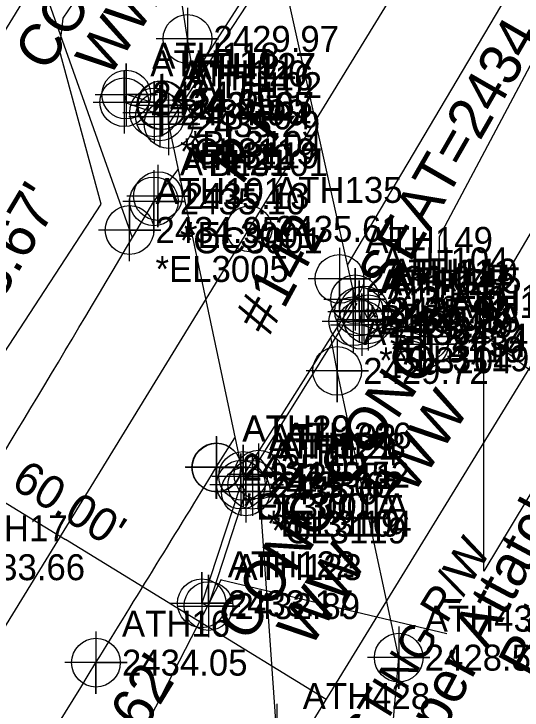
# Model space of a CAD drawing. Extents: x 983976 to 986421, y 758828 to 761458.
# Drawn here: x 984809.7 to 984858.6, y 760052.1 to 760119.1 of the extents above; entities that cross this region are included whole.
import ezdxf

# ---------------------------------------------------------------- set-up
doc = ezdxf.new("R2010")
doc.units = 0
for name, color, linetype in [('COGO Default Chain', 7, 'Continuous'), ('CTL Secondary Horizontal and Vertical Leader', 7, 'Continuous'), ('CTL Secondary Horizontal and Vertical Text', 7, 'Continuous'), ('CTL Sheet Text', 7, 'Continuous'), ('Exist DTM Drainline Cogo Point CELL', 7, 'Continuous'), ('Exist DTM Regular Point CELL', 7, 'Continuous'), ('Exist DTM Regular Point Underwater CELL', 7, 'Continuous'), ('Exist Guardrail', 7, 'Continuous'), ('Exist Horizontal Alignment', 7, 'Continuous'), ('Exist Hydro Jurisdictional Stream or Body of Water', 7, 'Continuous'), ('Exist Property Iron Pin CELL', 7, 'Continuous'), ('Exist Property Iron Pin Cogo Elevation', 7, 'Continuous'), ('Exist Property Iron Pin Cogo Number', 7, 'Continuous'), ('Exist Property Iron Pin Text', 7, 'Continuous'), ('Exist Right of Way Line', 7, 'Continuous'), ('Exist Right of Way Line Text', 7, 'Continuous'), ('Exist Right of Way Width CELL', 7, 'Continuous'), ('Exist Roads EOP', 7, 'Continuous'), ('Exist Roads EOP Cogo Point CELL', 7, 'Continuous'), ('Exist Roads Soil', 7, 'Continuous'), ('Exist Roads Soil Cogo Comment', 7, 'Continuous'), ('Exist Roads Soil Cogo Elevation', 7, 'Continuous'), ('Exist Roads Soil Cogo Number', 7, 'Continuous'), ('Exist Roads Soil Cogo Point CELL', 7, 'Continuous'), ('Exist Structure Major Bridge Seat Cogo Comment', 7, 'Continuous'), ('Exist Structure Major Bridge Seat Cogo Elevation', 7, 'Continuous'), ('Exist Structure Major Bridge Seat Cogo Number', 7, 'Continuous'), ('Exist Structure Major Bridge Seat Cogo Point CELL', 7, 'Continuous'), ('Exist Structure Major Bridge Seat Top Elevation', 7, 'Continuous'), ('Exist Structure Major Bridge WW', 7, 'Continuous'), ('Exist Structure Major Bridge WW Cogo Comment', 7, 'Continuous'), ('Exist Structure Major Bridge WW Cogo Elevation', 7, 'Continuous'), ('Exist Structure Major Bridge WW Cogo Number', 7, 'Continuous'), ('Exist Structure Major Bridge WW Cogo Point CELL', 7, 'Continuous'), ('Exist Structure Major Bridge WW Text', 7, 'Continuous'), ('Exist Structure Major Deck Tunnel Box Culvert', 7, 'Continuous'), ('Exist Structure Major Deck Tunnel Box Culvert Cogo Comment', 7, 'Continuous'), ('Exist Structure Major Deck Tunnel Box Culvert Cogo Elevation', 7, 'Continuous'), ('Exist Structure Major Deck Tunnel Box Culvert Cogo Number', 7, 'Continuous'), ('Exist Structure Major Deck Tunnel Box Culvert Cogo Point CELL', 7, 'Continuous'), ('Exist Structure Major Deck Tunnel Box Culvert Text', 7, 'Continuous'), ('Exist Utilities Power Transformer CELL', 7, 'Continuous'), ('Exist Utilities Telephone Pole Leader', 7, 'Continuous'), ('Exist Utilities Telephone Pole Text', 7, 'Continuous'), ('Exist Utilities Telephone UG Cable SUE LOS C', 7, 'Continuous'), ('Exist Vegetation Woods Line', 7, 'Continuous')]:
    doc.layers.add(name, color=color, linetype=linetype)

msp = doc.modelspace()

# ---------------------------------------------------------------- linework, layer by layer
at = {"layer": 'COGO Default Chain'}
msp.add_line((984790.47, 760030.234), (984862.074, 760146.899), dxfattribs=at)
at = {"layer": 'Exist Guardrail'}
for p, q in [((984824.469, 760109.232), (984834.503, 760124.823)), ((984842.671, 760091.224), (984832.126, 760074.336))]:
    msp.add_line(p, q, dxfattribs=at)
at = {"layer": 'Exist Horizontal Alignment'}
msp.add_line((984790.47, 760030.234), (984862.074, 760146.899), dxfattribs=at)
at = {"layer": 'Exist Hydro Jurisdictional Stream or Body of Water'}
for points in [[(984827.066, 760112.31), (984826.358, 760116.652), (984820.043, 760157.784), (984809.834, 760195.884), (984798.987, 760237.514), (984800.737, 760260.977), (984804.203, 760288.203), (984847.36, 760365.08), (984869.621, 760385.916), (984871.863, 760387.268)], [(984800.619, 759968.566), (984818.293, 759984.477), (984835.163, 760005.552), (984843.8, 760023.761), (984846.689, 760057.108), (984840.766, 760084.703), (984840.17, 760087.938)], [(984793.936, 759973.558), (984809.362, 759990.771), (984821.775, 760009.83), (984828.882, 760021.21), (984834.949, 760049.656), (984833.195, 760074.723), (984832.908, 760076.484)]]:
    msp.add_lwpolyline(points, dxfattribs=at)
at = {"layer": 'Exist Property Iron Pin CELL'}
for radius in [2.203, 0.0707]:
    msp.add_circle((984832.29, 760098.372), radius, dxfattribs=at)
at = {"layer": 'Exist Right of Way Line'}
for p, q in [((984764.902, 760045.927), (984824.404, 760142.874)), ((984816.038, 760014.541), (984887.642, 760131.207))]:
    msp.add_line(p, q, dxfattribs=at)
at = {"layer": 'Exist Right of Way Width CELL'}
for p in [(984788.558, 760084.47), (984839.694, 760053.085)]:
    msp.add_line(p, (984814.619, 760068.475), dxfattribs=at)
at = {"layer": 'Exist Roads EOP'}
for p, q in [((984841.762, 760094.862), (984863.71, 760131.911)), ((984823.124, 760101.012), (984825.47, 760104.078)), ((984829.133, 760075.428), (984830.924, 760078.274))]:
    msp.add_line(p, q, dxfattribs=at)
for points in [[(984712.024, 759910.476), (984732.383, 759949.216), (984755.073, 759989.389), (984777.949, 760027.904), (984801.919, 760065.809), (984823.124, 760101.012)], [(984728.737, 759901.182), (984749.13, 759940.144), (984771.671, 759979.631), (984794.201, 760018.513), (984817.551, 760056.624), (984829.133, 760075.428)]]:
    msp.add_spline(points, degree=3, dxfattribs=at)
at = {"layer": 'Exist Roads EOP Cogo Point CELL'}
for points in [[(984823.518, 760104.527), (984823.518, 760098.527), (984823.518, 760101.527), (984826.518, 760101.527), (984820.518, 760101.527)], [(984823.124, 760104.012), (984823.124, 760098.012), (984823.124, 760101.012), (984826.124, 760101.012), (984820.124, 760101.012)], [(984840.989, 760096.558), (984840.989, 760090.558), (984840.989, 760093.558), (984843.989, 760093.558), (984837.989, 760093.558)], [(984829.133, 760078.428), (984829.133, 760072.428), (984829.133, 760075.428), (984832.133, 760075.428), (984826.133, 760075.428)], [(984829.165, 760078.394), (984829.165, 760072.394), (984829.165, 760075.394), (984832.165, 760075.394), (984826.165, 760075.394)], [(984817.551, 760059.624), (984817.551, 760053.624), (984817.551, 760056.624), (984820.551, 760056.624), (984814.551, 760056.624)]]:
    msp.add_lwpolyline(points, dxfattribs=at)
for centre in [(984823.518, 760101.527), (984823.124, 760101.012), (984840.989, 760093.558), (984829.133, 760075.428), (984829.165, 760075.394), (984817.551, 760056.624)]:
    msp.add_circle(centre, 2.344, dxfattribs=at)
at = {"layer": 'Exist Roads Soil'}
msp.add_lwpolyline([(984803.344, 760166.306), (984807.335, 760136.106), (984821.037, 760097.548)], dxfattribs=at)
at = {"layer": 'Exist Roads Soil Cogo Point CELL'}
msp.add_lwpolyline([(984820.784, 760095.261), (984820.784, 760101.261), (984820.784, 760098.261), (984823.784, 760098.261), (984817.784, 760098.261)], dxfattribs=at)
msp.add_circle((984820.784, 760098.261), 2.344, dxfattribs=at)
at = {"layer": 'Exist Structure Major Bridge Seat Cogo Point CELL'}
for points in [[(984820.955, 760110.291), (984826.955, 760110.291), (984823.955, 760110.291), (984823.955, 760113.291), (984823.955, 760107.291)], [(984839.309, 760089.475), (984845.309, 760089.475), (984842.309, 760089.475), (984842.309, 760092.475), (984842.309, 760086.475)], [(984829.6, 760073.75), (984835.6, 760073.75), (984832.6, 760073.75), (984832.6, 760076.75), (984832.6, 760070.75)]]:
    msp.add_lwpolyline(points, dxfattribs=at)
for centre in [(984823.955, 760110.291), (984842.309, 760089.475), (984832.6, 760073.75)]:
    msp.add_circle(centre, 2.344, dxfattribs=at)
at = {"layer": 'Exist Structure Major Bridge WW'}
for points in [[(984823.711, 760109.195), (984823.831, 760110.268), (984820.464, 760111.292), (984820.281, 760110.561), (984823.141, 760109.578), (984823.711, 760109.195)], [(984843.343, 760090.516), (984842.878, 760090.417), (984843.134, 760089.137), (984849.113, 760087.286), (984849.225, 760088.006), (984843.739, 760089.663), (984843.343, 760090.516)], [(984831.507, 760073.756), (984827.736, 760062.335), (984828.382, 760062.068), (984831.963, 760073.1), (984831.507, 760073.756)]]:
    msp.add_lwpolyline(points, dxfattribs=at)
at = {"layer": 'Exist Structure Major Bridge WW Cogo Point CELL'}
for points in [[(984817.464, 760111.292), (984823.464, 760111.292), (984820.464, 760111.292), (984820.464, 760114.292), (984820.464, 760108.292)], [(984817.281, 760110.561), (984823.281, 760110.561), (984820.281, 760110.561), (984820.281, 760113.561), (984820.281, 760107.561)], [(984820.831, 760110.268), (984826.831, 760110.268), (984823.831, 760110.268), (984823.831, 760113.268), (984823.831, 760107.268)], [(984820.141, 760109.578), (984826.141, 760109.578), (984823.141, 760109.578), (984823.141, 760112.578), (984823.141, 760106.578)], [(984820.711, 760109.195), (984826.711, 760109.195), (984823.711, 760109.195), (984823.711, 760112.195), (984823.711, 760106.195)], [(984839.878, 760090.417), (984845.878, 760090.417), (984842.878, 760090.417), (984842.878, 760093.417), (984842.878, 760087.417)], [(984840.343, 760090.516), (984846.343, 760090.516), (984843.343, 760090.516), (984843.343, 760093.516), (984843.343, 760087.516)], [(984840.739, 760089.663), (984846.739, 760089.663), (984843.739, 760089.663), (984843.739, 760092.663), (984843.739, 760086.663)], [(984840.134, 760089.137), (984846.134, 760089.137), (984843.134, 760089.137), (984843.134, 760092.137), (984843.134, 760086.137)], [(984846.225, 760088.006), (984852.225, 760088.006), (984849.225, 760088.006), (984849.225, 760091.006), (984849.225, 760085.006)], [(984846.113, 760087.286), (984852.113, 760087.286), (984849.113, 760087.286), (984849.113, 760090.286), (984849.113, 760084.286)], [(984828.507, 760073.756), (984834.507, 760073.756), (984831.507, 760073.756), (984831.507, 760076.756), (984831.507, 760070.756)], [(984828.963, 760073.1), (984834.963, 760073.1), (984831.963, 760073.1), (984831.963, 760076.1), (984831.963, 760070.1)], [(984824.736, 760062.335), (984830.736, 760062.335), (984827.736, 760062.335), (984827.736, 760065.335), (984827.736, 760059.335)], [(984825.382, 760062.068), (984831.382, 760062.068), (984828.382, 760062.068), (984828.382, 760065.068), (984828.382, 760059.068)]]:
    msp.add_lwpolyline(points, dxfattribs=at)
for centre in [(984820.464, 760111.292), (984820.281, 760110.561), (984823.831, 760110.268), (984823.141, 760109.578), (984823.711, 760109.195), (984842.878, 760090.417), (984843.343, 760090.516), (984843.739, 760089.663), (984843.134, 760089.137), (984849.225, 760088.006), (984849.113, 760087.286), (984831.507, 760073.756), (984831.963, 760073.1), (984827.736, 760062.335), (984828.382, 760062.068)]:
    msp.add_circle(centre, 2.344, dxfattribs=at)
at = {"layer": 'Exist Structure Major Deck Tunnel Box Culvert'}
msp.add_lwpolyline([(984824.546, 760108.45), (984831.704, 760074.585), (984842.487, 760091.592), (984835.146, 760124.686), (984824.546, 760108.45)], dxfattribs=at)
at = {"layer": 'Exist Structure Major Deck Tunnel Box Culvert Cogo Point CELL'}
for points in [[(984821.546, 760108.45), (984827.546, 760108.45), (984824.546, 760108.45), (984824.546, 760111.45), (984824.546, 760105.45)], [(984839.487, 760091.592), (984845.487, 760091.592), (984842.487, 760091.592), (984842.487, 760094.592), (984842.487, 760088.592)], [(984828.704, 760074.585), (984834.704, 760074.585), (984831.704, 760074.585), (984831.704, 760077.585), (984831.704, 760071.585)]]:
    msp.add_lwpolyline(points, dxfattribs=at)
for centre in [(984824.546, 760108.45), (984842.487, 760091.592), (984831.704, 760074.585)]:
    msp.add_circle(centre, 2.344, dxfattribs=at)
at = {"layer": 'Exist Utilities Power Transformer CELL'}
for points in [[(984826.358, 760119.652), (984826.358, 760113.652), (984826.358, 760116.652), (984829.358, 760116.652), (984823.358, 760116.652)], [(984840.766, 760087.703), (984840.766, 760081.703), (984840.766, 760084.703), (984843.766, 760084.703), (984837.766, 760084.703)], [(984833.195, 760077.723), (984833.195, 760071.723), (984833.195, 760074.723), (984836.195, 760074.723), (984830.195, 760074.723)], [(984846.689, 760060.108), (984846.689, 760054.108), (984846.689, 760057.108), (984849.689, 760057.108), (984843.689, 760057.108)], [(984834.949, 760052.656), (984834.949, 760046.656), (984834.949, 760049.656), (984837.949, 760049.656), (984831.949, 760049.656)]]:
    msp.add_lwpolyline(points, dxfattribs=at)
for centre in [(984826.358, 760116.652), (984840.766, 760084.703), (984833.195, 760074.723), (984846.689, 760057.108)]:
    msp.add_circle(centre, 2.344, dxfattribs=at)
at = {"layer": 'Exist Utilities Telephone Pole Leader'}
for p, q in [((984850.537, 760091.572), (984861.945, 760082.74)), ((984829.622, 760064.601), (984851.322, 760059.42))]:
    msp.add_line(p, q, dxfattribs=at)
at = {"layer": 'Exist Utilities Telephone UG Cable SUE LOS C'}
for points in [[(984850.543, 760091.655), (984850.627, 760097.643), (984859.639, 760114.607), (984864.144, 760121.689), (984870.985, 760135.648), (984883.311, 760156.929), (984894.357, 760176.432), (984907.483, 760199.308), (984916.105, 760217.14), (984924.076, 760237.745), (984929.153, 760256.453), (984933.619, 760271.108), (984938.949, 760285.269), (984944.259, 760311.94), (984949.818, 760340.507), (984962.189, 760379.55), (984968.577, 760393.245)], [(984735.48, 759996.35), (984742.018, 759994.164), (984745.761, 759995.104), (984748.488, 759998.937), (984763.623, 760023.792), (984778.86, 760050.581), (984792.164, 760067.072), (984808.722, 760086.443), (984818.045, 760100.742), (984814.058, 760115.562), (984814.401, 760118.642), (984818.244, 760124.329), (984819.704, 760125.325), (984838.189, 760141.042), (984839.77, 760142.811), (984839.369, 760146.124)], [(984783.925, 759973.591), (984781.685, 759976.686), (984784.559, 759981.984), (984794.071, 760003.928), (984803.972, 760021.08), (984819.837, 760045.635), (984829.645, 760064.662)]]:
    msp.add_lwpolyline(points, dxfattribs=at)
at = {"layer": 'Exist Vegetation Woods Line'}
msp.add_lwpolyline([(984967.644, 760252.528), (984854.892, 760065.426), (984854.892, 760090.279), (984898.176, 760163.89), (984932.461, 760244.19), (984956.171, 760337.546)], dxfattribs=at)

# ---------------------------------------------------------------- texts
at = {"layer": 'CTL Secondary Horizontal and Vertical Leader'}
for s, p in [('2429.97', (984828.858, 760115.402)), ('2429.72', (984843.266, 760083.453)), ('2429.52', (984835.695, 760073.473)), ('2428.58', (984849.189, 760055.858))]:
    msp.add_text(s, height=2.5, dxfattribs=at).set_placement(p)
at = {"layer": 'CTL Secondary Horizontal and Vertical Text'}
for s, p in [('ATH364', (984843.266, 760087.203)), ('ATH366', (984835.695, 760077.223)), ('ATH430', (984849.189, 760059.608)), ('ATH428', (984837.449, 760052.156))]:
    msp.add_text(s, height=2.5, dxfattribs=at).set_placement(p)
at = {"layer": 'CTL Sheet Text'}
msp.add_text('-BL- STA 18+50.45', height=5, rotation=56.98555, dxfattribs=at).set_placement((984855.523, 760024.903))
at = {"layer": 'Exist DTM Drainline Cogo Point CELL'}
for s, p in [('2435.13', (984826.018, 760100.277)), ('2435.10', (984825.624, 760099.762)), ('2436.04', (984843.489, 760092.308)), ('2435.02', (984831.633, 760074.178)), ('2435.03', (984831.665, 760074.144)), ('2433.66', (984804.419, 760064.559)), ('2434.05', (984820.051, 760055.374))]:
    msp.add_text(s, height=2.5, dxfattribs=at).set_placement(p)
at = {"layer": 'Exist DTM Regular Point CELL'}
for s, p in [('ATH22', (984826.018, 760104.027)), ('ATH21', (984825.624, 760103.512)), ('ATH149', (984843.489, 760096.058)), ('ATH19', (984831.633, 760077.928)), ('ATH20', (984831.665, 760077.894)), ('ATH17', (984804.419, 760068.309)), ('ATH16', (984820.051, 760059.124))]:
    msp.add_text(s, height=2.5, dxfattribs=at).set_placement(p)
at = {"layer": 'Exist DTM Regular Point Underwater CELL'}
for s, p in [('*OC3001', (984825.624, 760096.012)), ('*EL3001', (984826.018, 760096.527)), ('*BL3001A', (984843.489, 760088.558)), ('*OC3001A', (984831.633, 760070.428)), ('*EL3001A', (984831.665, 760070.394))]:
    msp.add_text(s, height=2.5, dxfattribs=at).set_placement(p)
at = {"layer": 'Exist Property Iron Pin Cogo Elevation'}
msp.add_text('2435.61', height=2.5, dxfattribs=at).set_placement((984834.79, 760097.122))
at = {"layer": 'Exist Property Iron Pin Cogo Number'}
msp.add_text('ATH135', height=2.5, dxfattribs=at).set_placement((984834.79, 760100.872))
at = {"layer": 'Exist Property Iron Pin Text'}
msp.add_text('P.K', height=4, rotation=52.51099, dxfattribs=at).set_placement((984831.54, 760102.477))
at = {"layer": 'Exist Right of Way Line Text'}
msp.add_text('EXISTING R/W', height=3.2, rotation=58.46015, dxfattribs=at).set_placement((984840.211, 760042.239))
at = {"layer": 'Exist Right of Way Width CELL'}
msp.add_text("60.00'", height=3.2, rotation=328.46015, dxfattribs=at).set_placement((984809.254, 760073.557))
at = {"layer": 'Exist Roads Soil Cogo Comment'}
msp.add_text('*EL3005', height=2.5, dxfattribs=at).set_placement((984823.284, 760093.261))
at = {"layer": 'Exist Roads Soil Cogo Elevation'}
msp.add_text('2434.95', height=2.5, dxfattribs=at).set_placement((984823.284, 760097.011))
at = {"layer": 'Exist Roads Soil Cogo Number'}
msp.add_text('ATH101', height=2.5, dxfattribs=at).set_placement((984823.284, 760100.761))
at = {"layer": 'Exist Structure Major Bridge Seat Cogo Comment'}
for s, p in [('*BL3104', (984826.455, 760105.291)), ('*BL3104', (984844.809, 760084.475)), ('*EL3104', (984835.1, 760068.75))]:
    msp.add_text(s, height=2.5, dxfattribs=at).set_placement(p)
at = {"layer": 'Exist Structure Major Bridge Seat Cogo Elevation'}
for s, p in [('2433.67', (984826.455, 760109.041)), ('2434.45', (984844.809, 760088.225)), ('2433.62', (984835.1, 760072.5))]:
    msp.add_text(s, height=2.5, dxfattribs=at).set_placement(p)
at = {"layer": 'Exist Structure Major Bridge Seat Cogo Number'}
for s, p in [('ATH127', (984826.455, 760112.791)), ('ATH125', (984844.809, 760091.975)), ('ATH128', (984835.1, 760076.25))]:
    msp.add_text(s, height=2.5, dxfattribs=at).set_placement(p)
at = {"layer": 'Exist Structure Major Bridge Seat Top Elevation'}
for s, rotation, p in [("SEAT=2434.45'", 60.13754, (984845.987, 760091.926)), ("SEAT=2433.67'", 59.25105, (984795.12, 760068.995)), ("SEAT=2433.62'", 58.50969, (984806.174, 760023.836))]:
    msp.add_text(s, height=4, rotation=rotation, dxfattribs=at).set_placement(p)
at = {"layer": 'Exist Structure Major Bridge WW Cogo Comment'}
for s, p in [('*CL3119', (984825.641, 760104.578)), ('*BL3119', (984826.211, 760104.195)), ('*BL3119', (984845.843, 760085.516)), ('*CL3119', (984846.239, 760084.663)), ('*BL3119', (984834.007, 760068.756)), ('*CL3119', (984834.463, 760068.1))]:
    msp.add_text(s, height=2.5, dxfattribs=at).set_placement(p)
at = {"layer": 'Exist Structure Major Bridge WW Cogo Elevation'}
for s, p in [('2434.61', (984822.964, 760110.042)), ('2434.65', (984822.781, 760109.311)), ('2435.05', (984826.331, 760109.018)), ('2434.90', (984825.641, 760108.328)), ('2435.04', (984826.211, 760107.945)), ('2435.91', (984845.843, 760089.266)), ('2435.92', (984845.378, 760089.167)), ('2435.79', (984845.634, 760087.887)), ('2435.88', (984846.239, 760088.413)), ('2434.60', (984851.725, 760086.756)), ('2434.31', (984851.613, 760086.036)), ('2435.06', (984834.007, 760072.506)), ('2435.07', (984834.463, 760071.85)), ('2433.17', (984830.236, 760061.085)), ('2432.89', (984830.882, 760060.818))]:
    msp.add_text(s, height=2.5, dxfattribs=at).set_placement(p)
at = {"layer": 'Exist Structure Major Bridge WW Cogo Number'}
for s, p in [('ATH118', (984822.964, 760113.792)), ('ATH119', (984822.781, 760113.061)), ('ATH117', (984826.331, 760112.768)), ('ATH120', (984825.641, 760112.078)), ('ATH116', (984826.211, 760111.695)), ('ATH111', (984845.378, 760092.917)), ('ATH110', (984845.843, 760093.016)), ('ATH115', (984846.239, 760092.163)), ('ATH112', (984845.634, 760091.637)), ('ATH114', (984851.725, 760090.506)), ('ATH113', (984851.613, 760089.786)), ('ATH121', (984834.007, 760076.256)), ('ATH124', (984834.463, 760075.6)), ('ATH122', (984830.236, 760064.835)), ('ATH123', (984830.882, 760064.568))]:
    msp.add_text(s, height=2.5, dxfattribs=at).set_placement(p)
at = {"layer": 'Exist Structure Major Bridge WW Text'}
for s, p in [('CONC', (984812.793, 760113.32)), (' WW', (984817.905, 760111.525)), ('CONC', (984842.052, 760073.194)), (' WW', (984847.164, 760071.399)), ('CONC', (984832.189, 760058.445)), (' WW', (984837.301, 760056.65))]:
    msp.add_text(s, height=4, rotation=56.34707, dxfattribs=at).set_placement(p)
at = {"layer": 'Exist Structure Major Deck Tunnel Box Culvert Cogo Comment'}
msp.add_text('*BL3101', height=2.5, dxfattribs=at).set_placement((984827.046, 760103.45))
at = {"layer": 'Exist Structure Major Deck Tunnel Box Culvert Cogo Elevation'}
for s, p in [('2435.29', (984827.046, 760107.2)), ('2436.10', (984844.987, 760090.342)), ('2435.11', (984834.204, 760073.335))]:
    msp.add_text(s, height=2.5, dxfattribs=at).set_placement(p)
at = {"layer": 'Exist Structure Major Deck Tunnel Box Culvert Cogo Number'}
for s, p in [('ATH102', (984827.046, 760110.95)), ('ATH104', (984844.987, 760094.092)), ('ATH103', (984834.204, 760077.085))]:
    msp.add_text(s, height=2.5, dxfattribs=at).set_placement(p)
at = {"layer": 'Exist Structure Major Deck Tunnel Box Culvert Text'}
msp.add_text('#142', height=4, rotation=61.40271, dxfattribs=at).set_placement((984834.195, 760087.915))
at = {"layer": 'Exist Utilities Telephone Pole Text'}
for s, p in [('Telephone Copper Attatched to', (984833.688, 760017.409)), ('Bridge ', (984859.623, 760054.908))]:
    msp.add_text(s, height=4, rotation=61.94356, dxfattribs=at).set_placement(p)

doc.saveas('drawing.dxf')
